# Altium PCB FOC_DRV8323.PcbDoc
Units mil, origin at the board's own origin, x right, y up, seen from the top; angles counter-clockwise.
Board outline 1427.17 x 915.35 mil, 6 copper layers (Top Layer, GND1, GND, Sign, GND2, Bottom Layer), stack 32.112 mil thick; 72 components, 67 nets, 293 pads, 283 vias.
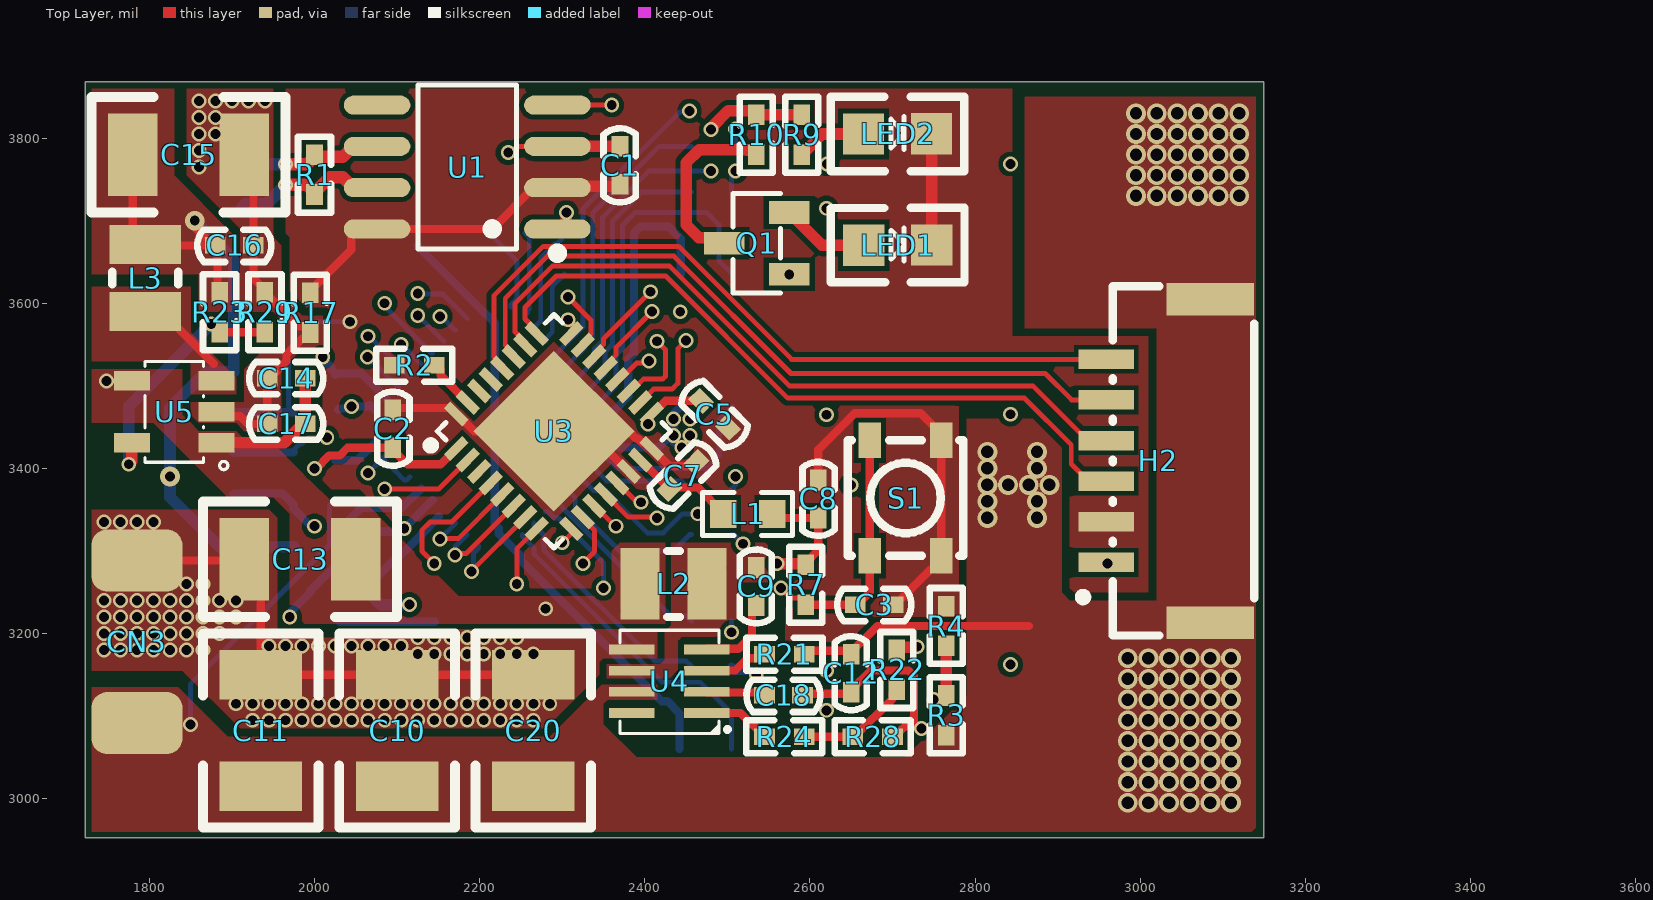
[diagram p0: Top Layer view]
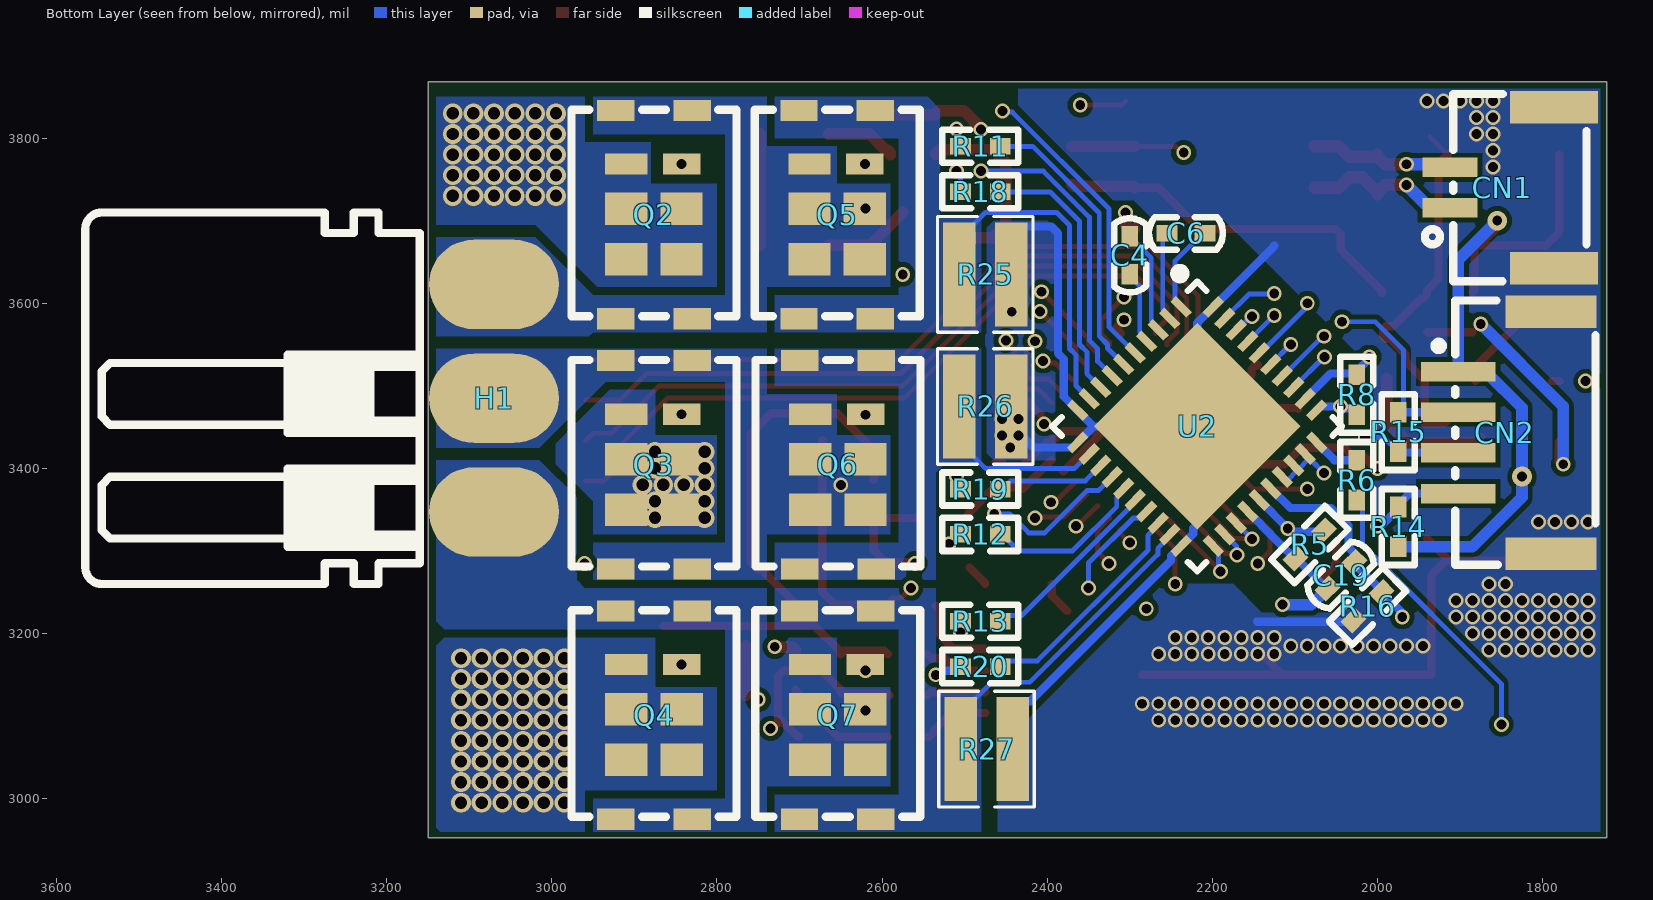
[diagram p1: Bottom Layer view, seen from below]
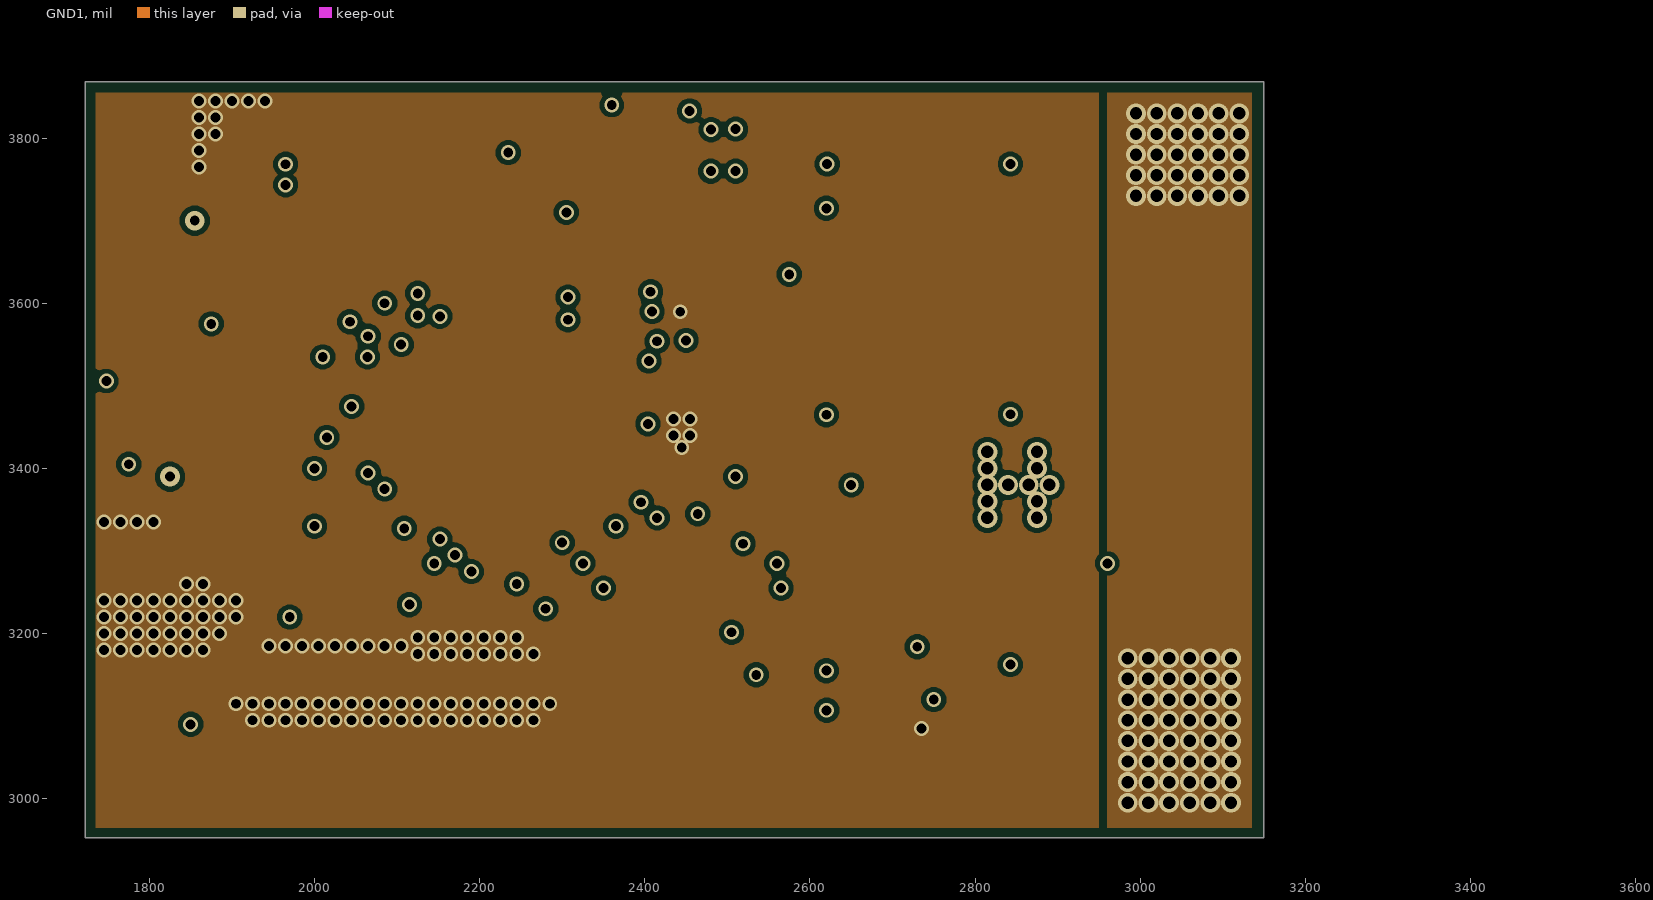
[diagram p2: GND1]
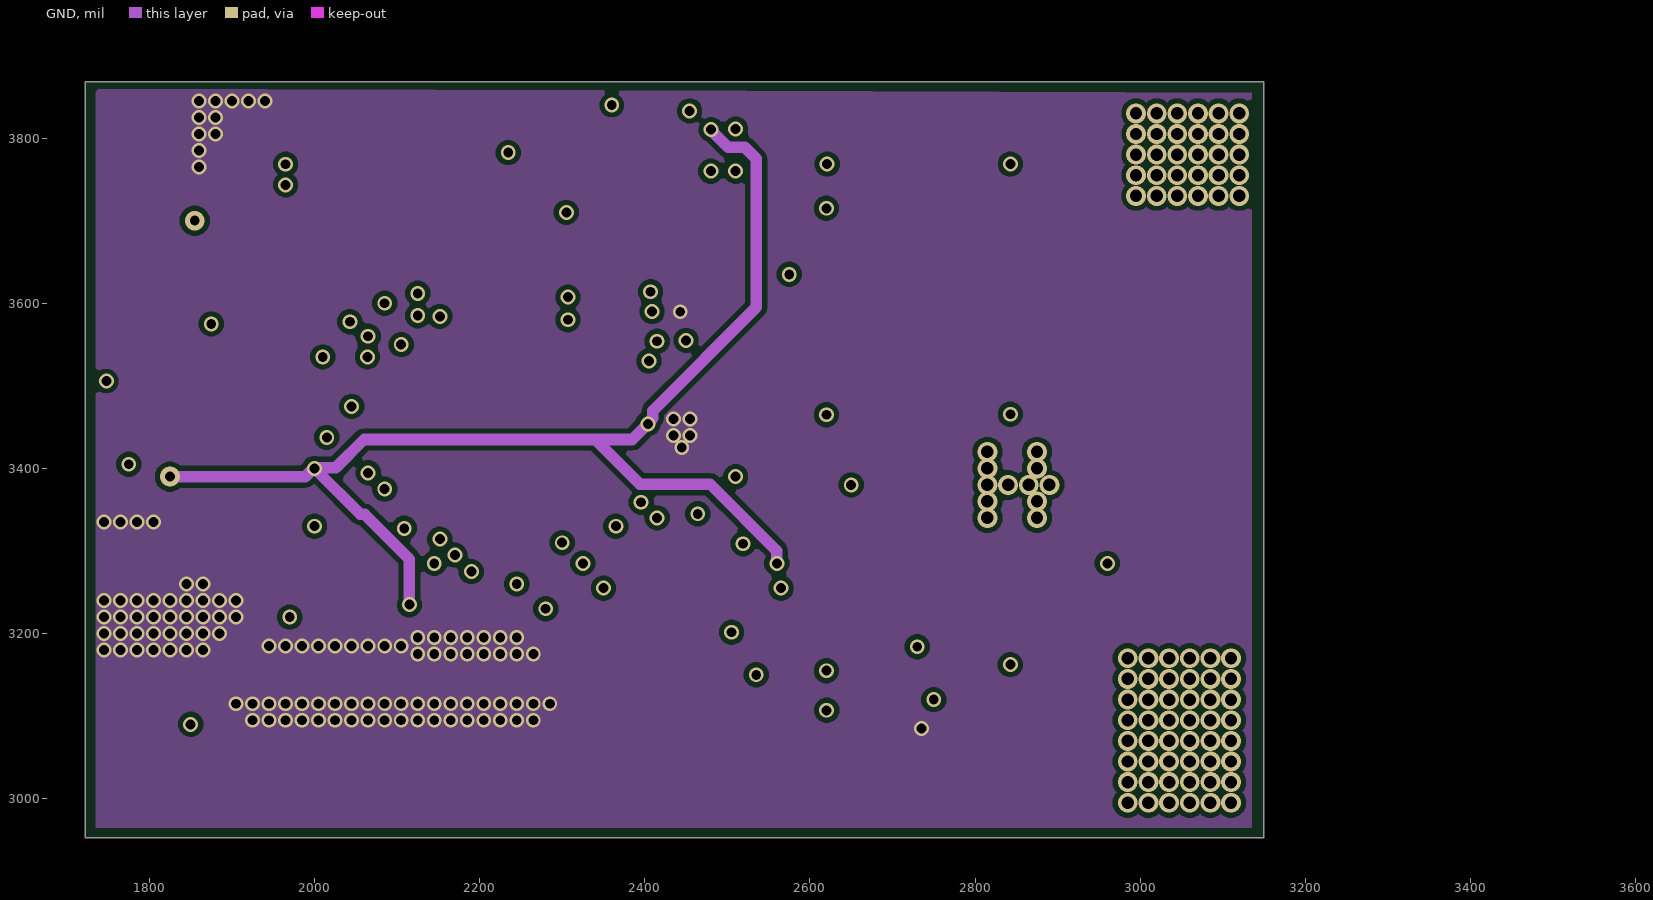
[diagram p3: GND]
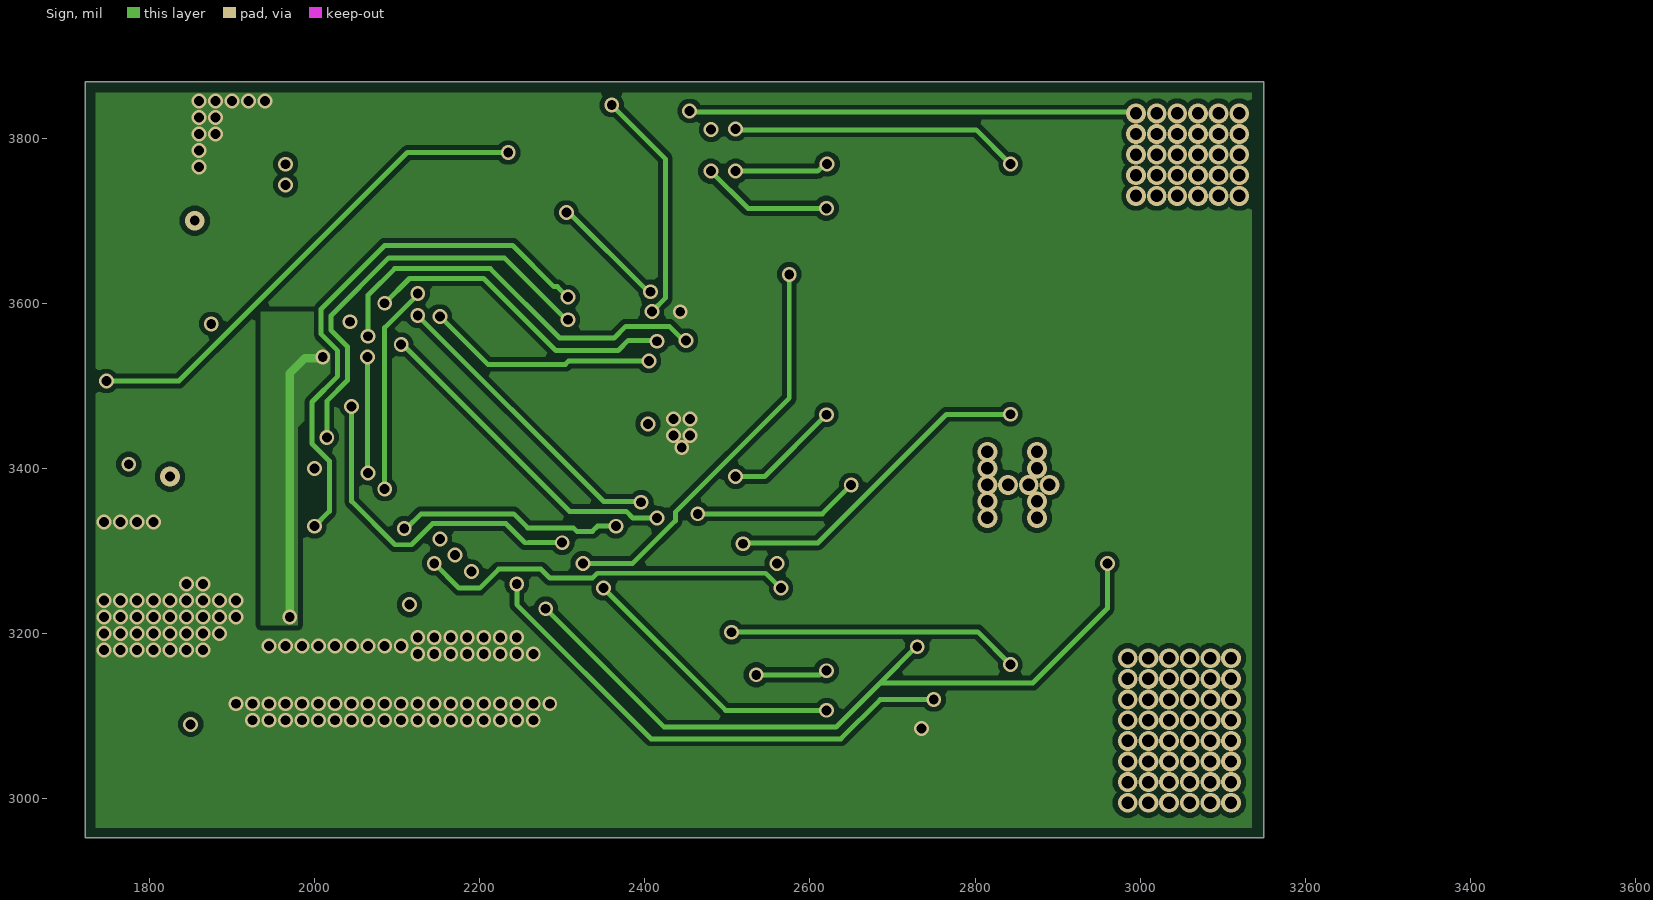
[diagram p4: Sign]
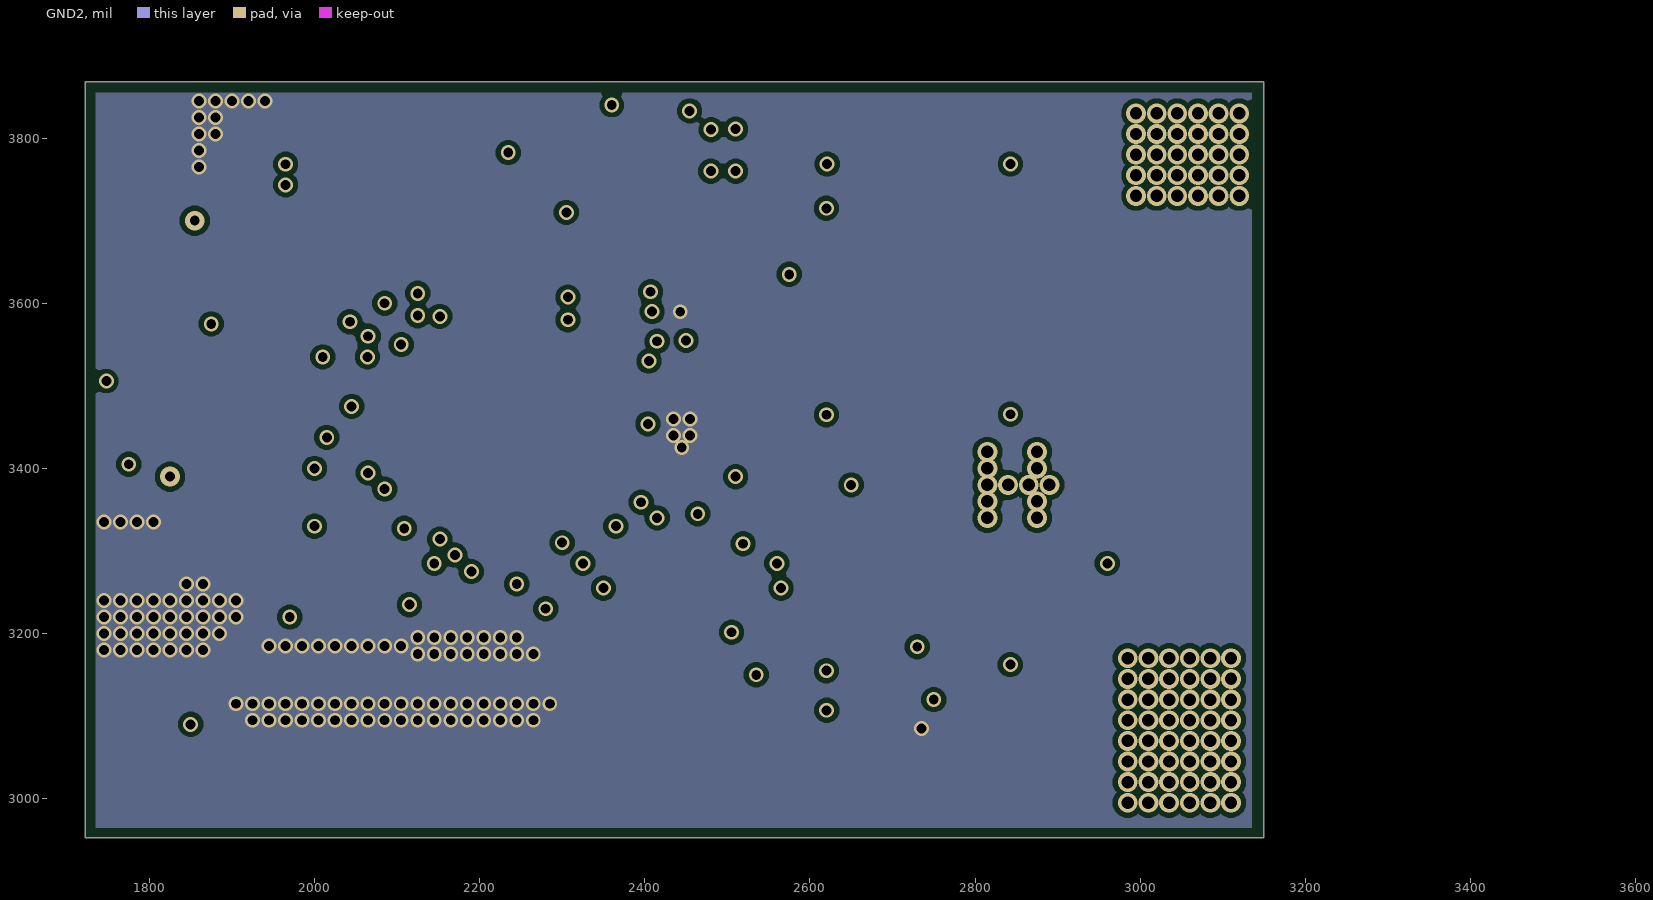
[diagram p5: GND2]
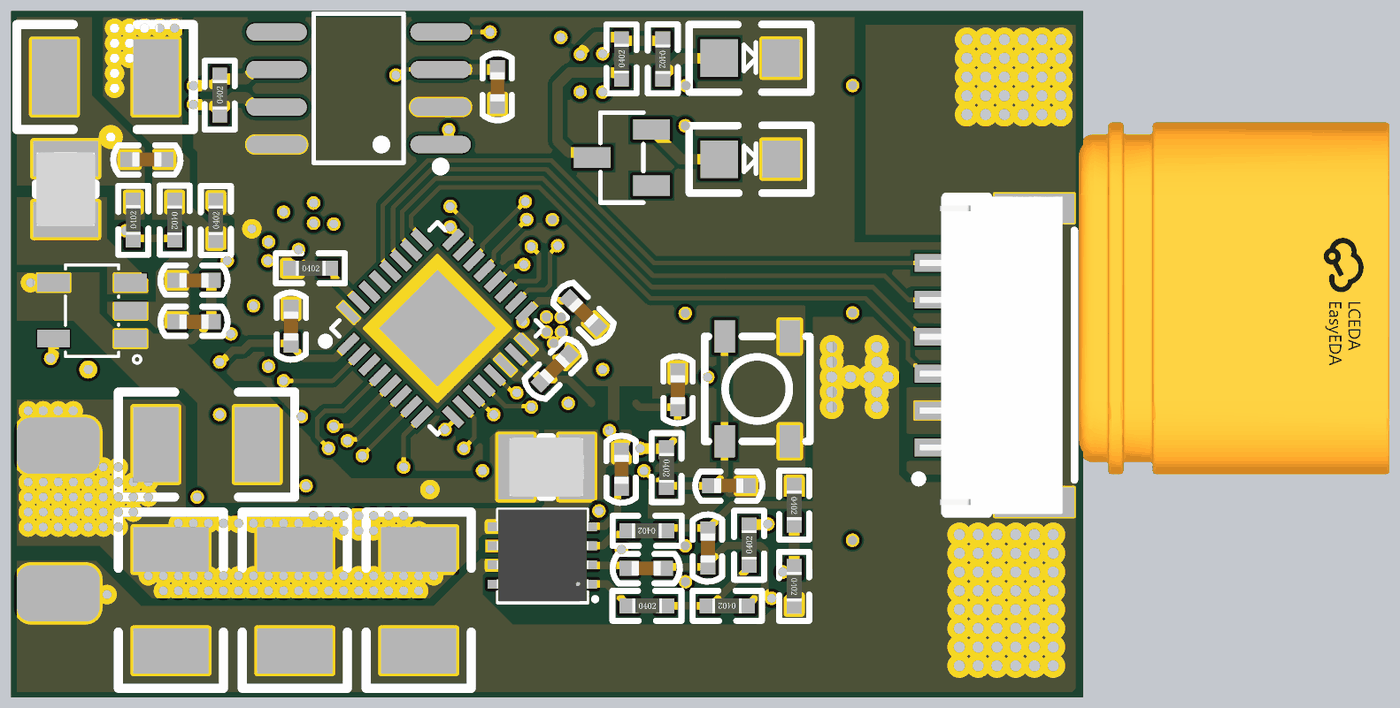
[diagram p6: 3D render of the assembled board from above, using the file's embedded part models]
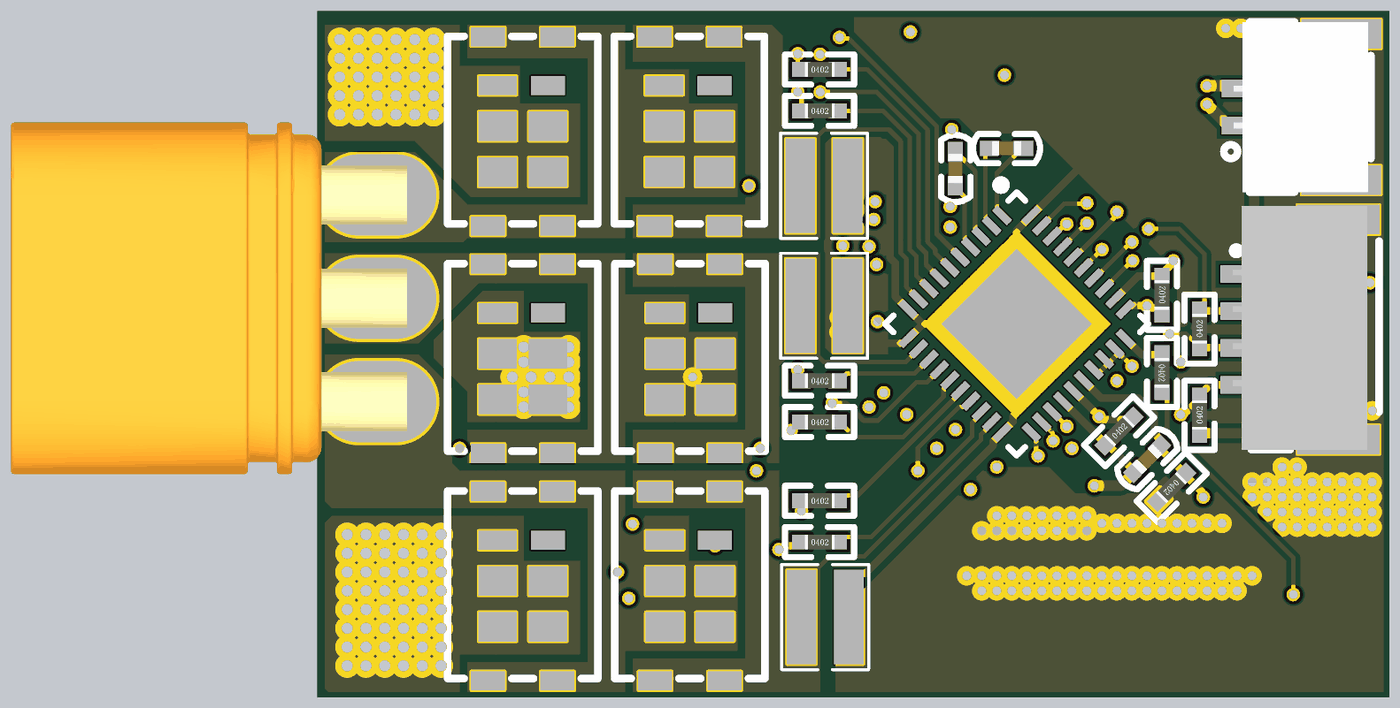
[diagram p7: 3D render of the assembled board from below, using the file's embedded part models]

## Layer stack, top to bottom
Top Solder: solder mask 0.4, Solder Resist, Dk 3.5
Top Layer: signal copper 1.4
Dielectric 2: prepreg 2.8, PP-006, Dk 4.1
GND1: signal copper 1.378
Dielectric 4: prepreg 2.8, PP-006, Dk 4.1
GND: signal copper 1.378
Dielectric 1: dielectric 12.6, FR-4, Dk 4.8
Sign: signal copper 1.378
Dielectric 5: prepreg 2.8, PP-006, Dk 4.1
GND2: signal copper 1.378
Dielectric 3: prepreg 2.8, PP-006, Dk 4.1
Bottom Layer: signal copper 1.4
Bottom Solder: solder mask 0.4, Solder Resist, Dk 3.5

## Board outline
1722.44,2952.76 1722.44,3868.11 3149.61,3868.11 3149.61,2952.76

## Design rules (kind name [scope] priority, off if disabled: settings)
Clearance [All] p1: gap=6 ignorepadtopadclearanceinfootprint=FALSE except(0: Arc-Hole Track-Hole SMDPad-Hole THPad-Hole Via-Hole Fill-Hole Poly-Hole Region-Hole Text-Hole)
DiffPairsRouting [All] p1: maxlimit=10 minlimit=10 mostfreqgap=10 toplayer_minwidth=15 toplayer_maxwidth=15 toplayer_prefwidth=15 midlayer1_minwidth=15 midlayer1_maxwidth=15 midlayer1_prefwidth=15 midlayer2_minwidth=15 midlayer2_maxwidth=15 midlayer2_prefwidth=15 midlayer3_minwidth=15 midlayer3_maxwidth=15 midlayer3_prefwidth=15 midlayer4_minwidth=15 midlayer4_maxwidth=15 midlayer4_prefwidth=15 bottomlayer_minwidth=15 bottomlayer_maxwidth=15 bottomlayer_prefwidth=15 maxuncoupledlength=500
HoleToHoleClearance [All] p1: gap=4 allowstackedmicrovias=TRUE
MinimumSolderMaskSliver [All] p1: minsoldermaskwidth=0
PlaneClearance [All] p1: clearance=8
PlaneConnect [All] p1: planeconnectstyle=Direct reliefexpansion=20 reliefentries=4 reliefconductorwidth=10 reliefairgap=10
PolygonConnect [All] p1: connectstyle=Direct reliefconductorwidth=10 reliefentries=4 polygonreliefangle="90 Angle" airgapwidth=10
RoutingVias [All] p1: holewidth=12 width=16 viastyle="Through Hole" minholewidth=10 minwidth=16 maxholewidth=28 maxwidth=50
SilkToSilkClearance [All] p1: silktosilkclearance=0
SilkToSolderMaskClearance [IsPad] p1: minsilkscreentomaskgap=0 clearancetoexposedcopper=TRUE
SolderMaskExpansion [All] p1: expansion=4 istentingtop=FALSE
Width [All] p1: maxlimit=14 minlimit=6 preferedwidth=10
23 further rules are at their usual default settings.

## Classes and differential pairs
differential pair CAN: +CAN_P -CAN_N

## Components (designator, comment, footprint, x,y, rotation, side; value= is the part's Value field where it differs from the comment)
C1 "100nF" c0402 2370,3745 r90 top
C2 "100nF" c0402 2095,3470 r270 top
C3 "100nF" c0402 2700,3235 r180 top
C4 "1uF" c0402 2300,3680 r270 bottom
C5 "100nF" c0402 2500,3450 r135 top
C6 "47nF" c0402 2210,3685 r0 bottom
C7 "100nF" c0402 2461.82,3406.82 r225 top
C8 "100nF" c0402 2610,3385 r270 top
C9 "100nF" c0402 2535,3235 r90 top
C10 "10uF" 1210 2100,3150 r270 top
C11 "10uF" 1210 1935,3150 r270 top
C12 "100nF" c0402 2650,3130 r90 top
C13 "10uF" 1210 1915,3290 r0 top
C14 "100nF" c0402 1943.82,3508.9 r0 top
C15 "10uF" 1210 1915,3780 r180 top
C16 "100nF" c0402 1925,3670 r180 top
C17 "1uF" c0402 1943.82,3453.9 r0 top
C18 "100nF" c0402 2590,3125 r180 top
C19 "100nF" c0402 2060,3255 r135 bottom
C20 "10uF" 1210 2265,3150 r270 top
CN1 "卧式CAN" "GH1.25 2P 卧式" 1849.16,3740 r90 bottom
CN2 "卧式STLINK" CONN-SMD_4P-P1.25_GH1.25-4P 1846.1,3443.35 r90 bottom
CN3 "XT30_1" XT30卧式焊盘 1785,3190 r0 top
H1 "MR30-M" MR30 3070,3485 r270 bottom
H2 "卧式GH1.25 6PIN" CONN-SMD_6P-P1.25_XYECONN_XY-GH1.25-6A61 3022.01,3409.13 r90 top
L1 "1008屏蔽电感" R0603 3889.19,3386.01 r180 top
L2 "1008屏蔽电感" IND-SMD_L2.5-W2.0 2435,3260 r0 top
L3 "1008屏蔽电感" IND-SMD_L2.5-W2.0 1795,3630.48 r270 top
LED1 "LED" led0805 2665.2,3670.35 r0 top
LED2 "LED" led0805 2665,3805 r0 top
Q1 "SS8050" SOT-23-3_L2.9-W1.3-P1.90-LS2.4-BR 2316.65,3827.51 r0 top
Q2 "IRF7480MTRPBF" TRS-SMD_IRF7480MTRPBF 2876.3,3707.44 r270 bottom
Q3 "IRF7480MTRPBF" TRS-SMD_IRF7480MTRPBF 2876.3,3404.31 r270 bottom
Q4 "IRF7480MTRPBF" TRS-SMD_IRF7480MTRPBF 2876.26,3101.18 r270 bottom
Q5 "IRF7480MTRPBF" TRS-SMD_IRF7480MTRPBF 2654.36,3707.44 r270 bottom
Q6 "IRF7480MTRPBF" TRS-SMD_IRF7480MTRPBF 2653.47,3404.31 r270 bottom
Q7 "IRF7480MTRPBF" TRS-SMD_IRF7480MTRPBF 2653.74,3101.18 r270 bottom
R1 "120Ω" R0402 2000,3731.8 r90 top
R2 "10K" R0402 2096.8,3525 r0 top
R3 "10K" R0402 2765,3125 r270 top
R4 "1K" R0402 2765,3233.2 r270 top
R5 "200k" R0402 2099.08,3290.92 r135 bottom
R6 "200k" R0402 2025,3410 r270 bottom
R7 "10K" R0402 2595,3283.2 r270 top
R8 "200k" R0402 2025,3465 r90 bottom
R9 "2K" R0402 2590,3828.2 r270 top
R10 "2KΩ" R0402 2535,3780 r90 top
R11 "2.2R" R0402 2505,3790 r180 bottom
R12 "2.2R" R0402 2505,3320 r180 bottom
R13 "2.2R" R0402 2505,3215 r180 bottom
R14 "10KΩ" R0402 1975,3305 r90 bottom
R15 "10KΩ" R0402 1975,3420 r90 bottom
R16 "0" R0402 1995,3250 r315 bottom
R17 "0" R0402 1994.88,3564.59 r90 top
R18 "2.2R" R0402 2505,3735 r180 bottom
R19 "2.2R" R0402 2505,3375 r180 bottom
R20 "2.2R" R0402 2505,3160 r180 bottom
R21 "10KΩ" R0402 2593.2,3175 r180 top
R22 "43KΩ" R0402 2705,3131.8 r90 top
R23 "232KΩ" R0402 1885,3565 r90 top
R24 "51KΩ" R0402 2545,3075 r0 top
R25 "0.001" R0612 2475,3635 r0 bottom
R26 "0.001" R0612 2475,3475 r0 bottom
R27 "0.001" R0612 2473.5,3060 r0 bottom
R28 "8.2KΩ" R0402 2700,3075 r180 top
R29 "51KΩ" R0402 1940,3613.2 r270 top
S1 "SW" KEY_SMD 2715.86,3364.14 r90 top
U1 "SN65HVD1050DR" SOIC-8_L4.9-W3.9-P1.27-LS6.0-BL 2185,3765 r90 top
U2 "DRV8323HRTAR" QFN-40_L6.0-W6.0-P0.50-BL-EP4.5 2226.52,3458.96 r315 bottom
U3 "STM32G431KBU3" UFQFPN-32_L5.0-W5.0-P0.50-BL-EP3.5 2286.98,3441.98 r315 top
U4 "MP9943" "QFN-8 3x3" 2475,3103.82 r180 top
U5 "TLV62569DBVR" SOT-23-5_L3.0-W1.7-P0.95-LS2.8-BR 1830,3465 r0 top

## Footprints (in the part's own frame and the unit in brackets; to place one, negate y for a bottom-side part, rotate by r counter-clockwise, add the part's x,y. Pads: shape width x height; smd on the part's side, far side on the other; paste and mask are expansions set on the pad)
1210 [mil]
  rect 60x100 smd: 1(0,0) 2(135,0)
  silkscreen extent -50,-70 185,70, body extent 4,-49 130,49, height 30
c0402 [mil]
  rect 25x20 smd: 1(-1,0) 2(45,0)
  silkscreen extent -23,-19 67,20, body extent 2,-10 42,10, height 20
CONN-SMD_4P-P1.25_GH1.25-4P [mm]
  rect 0.6x2.3 smd mask+0.051: 1(1.875,1.425) 2(0.625,1.425) 3(-0.625,1.425) 4(-1.875,1.425)
  rect 1x2.8 smd mask+0.051: 5(-3.725,-1.425) 6(3.725,-1.425)
  silkscreen extent -4.06,-2.8 4.06,2.16, body extent -4.07,-2.4 4.19,2.15, height 4.13
CONN-SMD_6P-P1.25_XYECONN_XY-GH1.25-6A61 [mm]
  rect 0.6x1.7 smd paste+0 mask+0.05: 1(-3.125,1.6) 2(-1.875,1.6) 3(-0.625,1.6) 4(0.625,1.6) 5(1.875,1.6) 6(3.125,1.6)
  rect 1x2.7 smd paste+0 mask+0.05: 7(4.975,-1.6) 8(-4.975,-1.6)
  silkscreen extent -5.38,-2.95 5.38,2.44, body extent -5.38,-2.55 5.39,2.3, height 4.34
"GH1.25 2P 卧式" [mm]
  rect 0.6x1.7 smd mask+0.051: 1(-0.625,1.602) 2(0.625,1.602)
  rect 1x2.7 smd mask+0.051: 3(2.475,-1.602) 4(-2.475,-1.598)
  silkscreen extent -2.88,-2.6 2.88,2.37, body extent -2.88,-2.51 2.88,2.05, height 4.13
IND-SMD_L2.5-W2.0 [mm]
  rect 1.2x2.2 smd: 1(1.028,0) 2(-1.028,0)
  silkscreen extent -0.2,-1.02 0.2,1.02, body extent -1.26,-1 1.26,1, height 1.2
KEY_SMD [mm]
  rect 1.1x0.7 smd: 1(-1.775,-1.1) 1(1.775,-1.1) 2(-1.775,1.1) 2(1.775,1.1)
  silkscreen extent -1.78,-1.78 1.78,1.78
led0805 [mil] "1/8W"
  rect 50x50 smd: 1(0,0) 2(82.3,0.2)
  silkscreen extent -40,-45 122,45, body extent 2,-25 80,25, height 20
MR30 [mm]
  oval 2.75x4 smd: 1(3.5,0) 2(0,0) 3(-3.5,0)
  silkscreen extent -5.72,-12.57 5.71,-2.29, body extent -5.95,-12.39 5.95,1.01, height 2.45
"QFN-8 3x3" [mm]
  rect 1.4x0.3 smd: 1(0,0) 2(0,-0.65) 3(0,-1.3) 4(0,-1.95) 5(2.3,-1.95) 6(2.3,-1.3) 7(2.3,-0.65) 8(2.3,0)
  silkscreen extent -0.64,-2.54 2.67,0.64, body extent -0.41,-2.53 2.69,0.57, height 0.94
QFN-40_L6.0-W6.0-P0.50-BL-EP4.5 [mm]
  rect 0.25x0.7 smd paste-100 mask+0.051: 1(-2.25,-2.659) 2(-1.75,-2.659) 3(-1.25,-2.659) 4(-0.75,-2.659) 5(-0.25,-2.659) 6(0.25,-2.659) 7(0.75,-2.659) 8(1.25,-2.659) 9(1.75,-2.659) 10(2.25,-2.659) 21(2.25,3.241) 22(1.75,3.241) 23(1.25,3.241) 24(0.75,3.241) 25(0.25,3.241) 26(-0.25,3.241) 27(-0.75,3.241) 28(-1.25,3.241) 29(-1.75,3.241) 30(-2.25,3.241)
  rect 0.7x0.25 smd paste-100 mask+0.051: 11(2.95,-1.958) 12(2.95,-1.459) 13(2.95,-0.958) 14(2.95,-0.459) 15(2.95,0.042) 16(2.95,0.541) 17(2.95,1.042) 18(2.95,1.541) 19(2.95,2.041) 20(2.95,2.541) 31(-2.95,2.541) 32(-2.95,2.041) 33(-2.95,1.541) 34(-2.95,1.042) 35(-2.95,0.541) 36(-2.95,0.042) 37(-2.95,-0.459) 38(-2.95,-0.958) 39(-2.95,-1.459) 40(-2.95,-1.958)
  rect 4.5x4.5 smd paste-100 mask+0.051: 41(0,0.292)
  silkscreen extent -3.15,-3.56 3.15,3.44
R0402 [mil] "1/16W"
  rect 25x20 smd: 1(0,0) 2(48.2,0)
  silkscreen extent -22,-20 70,20, body extent 5,-10 44,10, height 14
R0603 [mil]
  rect 31.75x34.02 smd paste-3937.01 mask+2: 1(1334.87,41.01) 2(1394.19,41.01)
  silkscreen extent 1310,15 1419,67, body extent 1334,24 1396,56, height 18
R0612 [mm]
  rect 1x3.2 smd paste+0 mask+0.051: 1(-0.8,0) 2(0.8,0)
  silkscreen extent -1.47,-1.78 1.47,1.78
SOIC-8_L4.9-W3.9-P1.27-LS6.0-BL [mm]
  oval 0.588x2.045 smd mask+0.051: 1(-1.905,-2.772) 2(-0.635,-2.772) 3(0.635,-2.772) 4(1.905,-2.772) 5(1.905,2.772) 6(0.635,2.772) 7(-0.635,2.772) 8(-1.905,2.772)
  silkscreen extent -2.8,-2.92 2.53,1.52, body extent -2.45,-3 2.45,3, height 1.75
SOT-23-3_L2.9-W1.3-P1.90-LS2.4-BR [mm]
  rect 1.25x0.7 smd: 1(6.562,-4.885) 2(6.562,-2.985) 3(4.562,-3.935)
  silkscreen extent 4.84,-5.46 6.29,-2.41, body extent 4.19,-5.39 6.99,-2.49, height 1.3
SOT-23-5_L3.0-W1.7-P0.95-LS2.8-BR [mm]
  rect 1.1x0.6 smd paste+0 mask+0.051: 1(1.3,-0.861) 2(1.3,0.089) 3(1.3,1.039) 4(-1.3,1.039) 5(-1.3,-0.861)
  silkscreen extent -0.9,-1.69 1.65,1.64
TRS-SMD_IRF7480MTRPBF [mm]
  rect 0.65x1.15 smd paste+0 mask+0.051: 1(-1.555,0.85) 7(-3.205,1.175) 8(-3.205,-1.175) 9(3.205,-1.175) 10(3.205,1.175)
  rect 1x1.3 smd paste+0 mask+0.051: 2(-0.175,0.85) 3(1.375,0.85) 4(1.375,-0.85) 5(-0.175,-0.85)
  rect 0.65x1.3 smd paste+0 mask+0.051: 6(-1.555,-0.85)
  silkscreen extent -3.22,-2.54 3.13,2.54
UFQFPN-32_L5.0-W5.0-P0.50-BL-EP3.5 [mm]
  rect 0.28x0.8 smd paste-100 mask+0.051: 1(-1.75,-2.392) 2(-1.25,-2.392) 3(-0.75,-2.392) 4(-0.25,-2.392) 5(0.25,-2.392) 6(0.75,-2.392) 7(1.25,-2.392) 8(1.75,-2.392) 17(1.75,2.609) 18(1.25,2.608) 19(0.75,2.609) 20(0.25,2.608) 21(-0.25,2.608) 22(-0.75,2.608) 23(-1.25,2.608) 24(-1.75,2.608)
  rect 0.8x0.28 smd paste-100 mask+0.051: 9(2.5,-1.642) 10(2.5,-1.142) 11(2.5,-0.642) 12(2.5,-0.142) 13(2.5,0.358) 14(2.5,0.858) 15(2.5,1.358) 16(2.5,1.858) 25(-2.5,1.858) 26(-2.5,1.358) 27(-2.5,0.858) 28(-2.5,0.358) 29(-2.5,-0.142) 30(-2.5,-0.642) 31(-2.5,-1.142) 32(-2.5,-1.642)
  rect 3.5x3.5 smd paste-100 mask+0.051: 33(0,0.108)
  silkscreen extent -2.54,-3.01 2.54,2.65
XT30卧式焊盘 [mil]
  rrect50% 110x75 smd: 1(0,98.43) 2(0,-98.43)

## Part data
C1 C9 C12 C14 C15 C16 C17 C18: library part 0402贴片电容, "贴片电容0402"
C2 C3 C4 C5 C6 C7 C8 C19: library part CC0201JRX7R9BB101
C10 C11 C13 C20: library part 1210贴片电容, "1210贴片电容"
H1: BOM_Manufacturer=AMASS(艾迈斯)
LED1 LED2: library part 0805贴片LED, "0805贴片LED"
Q1: library part 2N2222, "三极管"
R1 R10 R14 R15 R21 R22 R23 R24 R28 R29: library part 0402贴片电阻, "0402贴片电阻"
R2 R3 R4 R5 R6 R7 R8 R9 R16 R17: library part 2.2R, BOM_Manufacturer=UniOhm, BOM_Manufacturer Part=0603WAJ022JT5E
R11 R12 R13 R18 R19 R20: BOM_Manufacturer=UniOhm, BOM_Manufacturer Part=0603WAJ022JT5E
R25 R26 R27: library part 0.0005, BOM_Manufacturer=RALEC(旺诠), BOM_Manufacturer Part=LR2512-23R0005J4
S1: "开关"
U1: "CAN芯片", JLCPCB Part Class="Extended Part", LCSC Part Name=4.5V~5.5V, Manufacturer=TI(德州仪器), Operating Temperature=-40℃~+125℃, Supply Current=50mA

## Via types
v1: diameter 18, hole 12, Top Layer to Bottom Layer, 191 vias
v2: diameter 24, hole 15, Top Layer to Bottom Layer, 90 vias
v3: diameter 24, hole 12, Top Layer to Bottom Layer, 2 vias

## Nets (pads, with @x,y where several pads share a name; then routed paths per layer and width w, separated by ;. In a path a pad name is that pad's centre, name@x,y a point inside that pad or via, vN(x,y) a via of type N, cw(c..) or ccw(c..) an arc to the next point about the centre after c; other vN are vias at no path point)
5V: C1.2 C13.2 C14.2 C17.2 H2.1 L2.2 R22.2 U1.3 U5.1 U5.4 | length 1962
  Top Layer w6: v1(2234.68,3782.51) 2237.39,3782.51 2244.88,3790 U1.3
  Top Layer w10: U5.4 U5.4@1788.66,3505.91 ; U5.1@1874.37,3437.91 U5.1 ; C13.2@2050,3310 C13.2 2050,3285 C13.2@2065,3270 ; L2.2@2375.9,3227.24 2394.52,3245.86 L2.2
  Top Layer w14: U5.1 1924.73,3431.1 1924.94,3430.9 1963.32,3430.9 1986.32,3453.9 C17.2 C14.2 ; U1.3 C1.2 ; R22.2 2705,3180.23 2708,3183.23 2729.23,3183.23 v1(2730,3184)
  Sign w6: v1(1748.03,3505.76) 1835.76,3505.76 2112.51,3782.51 v1(2234.68,3782.51) ; v1(2280,3230) 2423.46,3086.54 2631.54,3086.54 2685,3140 ; v1(2730,3184) 2729,3184 2685,3140 ; v1(2960.27,3284.92) 2960.27,3230.27 2870,3140 2685,3140
+3.3V: C2.2 C5.2 C8.2 C15.2 C16.2 C19.1 CN2.1 L1.1 L3.2 R5.1 R7.1 R9.1 R10.2 R14.1 R23.2 U2.24 U3.1 U3.17 | length 3180.9
  Top Layer w10: C15.2 1780,3685.96 L3.2 1795.96,3670 C16.2@1877.5,3670 ; v3(1855,3700) 1856.15,3698.85 1856.15,3691.35 C16.2@1877.5,3670 ; R23.2 1882.5,3615.7 1882.5,3667.5 C16.2 C16.2@1877.5,3670 ; v1(2000,3400) 2002.16,3400 2017.84,3415.67 2030.62,3415.67 2039.95,3425 C2.2 2095,3422.5 2112.5,3405 2152.56,3405 U3.1 U3.1@2164.44,3416.88 ; U3.17 2409.04,3465.89 2424.97,3481.82 2457.57,3481.82 2459.34,3483.59 2466.41,3483.59 C5.2 ; L1.1 2559.32,3340 C8.2 2610,3300.7 R7.1@2595,3285.7
  Top Layer w14: v1(2480.26,3810.24) 2481.02,3811.01 2481.02,3813.14 2500.89,3833 2532,3833 2535,3830 R10.2 R9.1 ; v1(2560,3285) 2560.38,3284.62 2593.92,3284.62 R7.1@2595,3285.7
  GND w14: v3(1825,3390) 1988.92,3390 1998.92,3400 v1(2000,3400) 2000.77,3400.77 2025.77,3400.77 2060,3435 2340,3435 ; v1@2001.85,3400 2001.31,3399.46 2001.31,3398.69 2055.65,3344.35 2060.65,3344.35 2115,3290 v1(2115,3235) ; v1(2403.82,3453.89) 2384.93,3435 2340,3435 ; v1@2405.67,3453.13 2404.58,3454.21 2404.58,3455.74 2409.58,3460.74 2409.58,3469.58 2535,3595 2535,3775 2521,3789 2500.89,3789 2480.26,3809.63 v1(2480.26,3810.24) ; v1@2560,3285.54 2560,3300 2479,3381 2394,3381 2340,3435
  Bottom Layer w10: C19.1 2061.58,3254.29 2098.21,3290.92 2100.13,3290.92 2116.58,3307.37 2117.03,3307.37 2129.91,3320.25 2129.91,3320.7 U2.24@2150.9,3341.69
  Bottom Layer w14: v3(1855,3700) 1902.2,3652.8 CN2.1 1868.74,3517.17 1825,3473.43 v3(1825,3390) 1825,3365 1885,3305 R14.1 ; C19.1 2080,3235 v1(2115,3235)
AGND: C19.2 R8.2 R16.1 U2.26 U2.32 | length 699.5
  Sign w10: v1(1970,3220) 1970,3515 1988.47,3533.47 2008.47,3533.47 v1(2010,3535)
  Bottom Layer w10: v1(1970,3220) 1971.15,3221.15 1971.15,3226.15 R16.1 1995,3251.82 2028.18,3285 C19.2 2026.41,3288.59 2026.41,3295.66 2035.08,3304.33 2035.08,3330.93 2056.06,3351.91 2105.55,3351.91 U2.26 ; v1(2010,3535) 2010,3532.84 2020,3522.84 2020,3520.7 2025,3515.7 R8.2 2026.8,3515 2056.81,3515 U2.32
CAL: R8.1 U2.31 U3.9 | length 484.7
  Top Layer w6: v1(2300,3310) 2312,3322 2312,3325.55 U3.9
  Sign w6: v1(2045,3475) 2045,3360 2097.5,3307.5 2117.5,3307.5 2143,3333 2232,3333 2255.03,3309.97 2260,3309.97 ; 2260.03,3310 v1(2300,3310)
  Bottom Layer w10: R8.1@2028.41,3470.91 2030,3472.5 2040.88,3472.5 2044.86,3476.49 v1@2045,3476.49 ; v1(2045,3475) 2065.89,3475 2067.38,3476.49 2067.49,3476.49 U2.31
CAN_N: CN1.2 R1.2 U1.6 | length 174.1
  Top Layer w15: v1(1965,3768.4) 1990.9,3768.4 2000,3777.5 R1.2 ; R1.2@2002.5,3777.5 2034.31,3777.5 2046.81,3790 U1.6
  Bottom Layer w15: CN1.2 1916.02,3768.4 v1(1965,3768.4)
CAN_P: CN1.1 R1.1 U1.7 | length 194.2
  Top Layer w15: v1(1965,3743.4) 1990.9,3743.4 R1.1@2000,3734.3 ; R1.1 R1.1@2000,3734.3 ; U1.7 2046.81,3740 2034.31,3752.5 2018.2,3752.5 R1.1@2000,3734.3
  Bottom Layer w15: CN1.1 1916.54,3719.7 1941.3,3719.7 v1(1965,3743.4)
DGND: C1.1 C2.1 C3.1 C5.1 C7.1 C8.1 CN2.2 H2.2 LED1.2 LED2.2 R2.1 R4.1 R15.2 R17.2 S1.1 U1.2 U1.8 U3.14 U3.16 U3.32 U3.33 | length 1733.9
  Top Layer w10: R17.2 1994.88,3615.29 2044.65,3665.06 2044.65,3683.93 2050.73,3690 U1.8 2215.47,3690 2265.47,3740 U1.2 ; C2.1@2095.9,3471.9 2097.12,3473.12 2164.44,3473.12 U3.32 2172.41,3465.88 2193.29,3445 U3.33 U3.33@2331.75,3445 ; U3.14 U3.33@2331.75,3445 ; C7.1 2455.46,3407.53 2450.9,3402.97 2430.18,3402.97 2409.04,3424.11 U3.16 2401.08,3431.35 2396.57,3431.35 2391.71,3436.22 2389.14,3436.22 2380.36,3445 U3.33@2331.75,3445 ; C5.1@2500.71,3447.5 C5.1 ; C8.1 2610,3422.46 2654.21,3466.68 2734.38,3466.68 2759.16,3441.9 2759.16,3434.02 2759.16,3294.26 2759.16,3286.38 2750.38,3277.61 2746.11,3277.61 2703.5,3235 C3.1
  Top Layer w14: U1.2 2295.9,3741.75 2367.75,3741.75 C1.1 ; LED1.2 LED2.2@2747.5,3805
  Bottom Layer w6: R15.2 1968.23,3474.97 1968.23,3543.23 2002.62,3577.62 v1(2042.81,3577.62)
  Bottom Layer w10: CN2.2 1902.32,3468.08 1974.88,3468.08 R15.2
DVDD: U2.27 U2.28 U2.29 U2.33 | length 275.5
  Sign w6: v1(2064.17,3535) 2064.41,3534.76 2064.41,3395.16 v1(2065.01,3394.56)
  Bottom Layer w6: v1(2064.17,3535) 2064.83,3535 2101.48,3498.34 U2.33 ; v1(2065.01,3394.56) 2065.01,3394.72 2080.52,3410.24 2080.52,3410.88 2083.72,3410.88 2094.92,3399.67 U2.28@2097.64,3399.67 ; U2.29@2083.72,3413.59 U2.29 ; U2.28 U2.28@2097.64,3399.67 ; U2.27 2111.56,3385.76 2108.84,3385.76 2097.64,3396.96 U2.28@2097.64,3399.67
FDCAN_RX: U1.4 U3.21 | length 432.4
  Top Layer w6: U1.4@2305,3845 2310,3840 v1(2360,3840) ; U3.21 2352.63,3524.74 2365,3537.11 2365,3546.18 v1(2408.82,3590)
  Sign w6: v1(2360,3840) 2425,3775 2425,3606.18 v1(2408.82,3590)
FDCAN_TX: U1.1 U3.22 | length 281.5
  Top Layer w6: U1.1 U1.1@2297.43,3686.72 ; U3.22 2338.71,3539.03 2350,3550.31 2350,3556.93 v1(2407,3613.93)
  Top Layer w14: U1.1 2300.77,3690 2305,3694.23 v1(2305,3710)
  Sign w6: v1(2305,3710) 2307.97,3710 2404.03,3613.93 v1(2407,3613.93)
M0_AH: U2.34 U3.18 | length 677.5
  Top Layer w6: U3.18 2410.59,3496 2433.02,3496 2440,3502.98 2440,3545 v1(2450,3555)
  Sign w6: v1(2065,3560) 2065,3610 2097,3642 2213,3642 2297,3558 2363,3558 2377,3572 2429.75,3572 2446.75,3555 v1(2450,3555)
  Bottom Layer w6: v1(2065,3560) 2066.24,3560 2114.16,3512.09 U2.34
M0_AL: U2.35 U3.12 | length 505.4
  Top Layer w6: U3.12 2380.07,3341 2414,3341 v1(2415,3340)
  Sign w6: v1(2105,3550) 2106.92,3550 2308.92,3348 2377.46,3348 2385.46,3340 v1(2415,3340)
  Bottom Layer w6: v1(2105,3550) 2105.33,3550 U2.35
M0_BH: U2.36 U3.19 | length 568.1
  Top Layer w6: U3.19 2384.03,3493.73 2398.3,3508 2421.49,3508 2425,3511.51 2425,3544 v1(2415,3554)
  Sign w6: v1(2085,3600) 2115,3630 2205,3630 2292.29,3542.71 2367.71,3542.71 2380,3555 2414,3555 v1(2415,3554)
  Bottom Layer w6: v1(2085,3600) 2085,3597.29 2089,3593.29 2089,3591.96 2141.03,3539.93 U2.36
M0_BL: U2.37 U3.13 | length 448
  Top Layer w6: U3.13 2367.1,3382.35 2388.15,3361.3 2393.29,3361.3 v1(2395.59,3359)
  Sign w6: v1(2125,3585) 2350,3360 2394.59,3360 v1(2395.59,3359)
  Bottom Layer w6: v1(2125,3585) 2125.51,3585 2156.66,3553.85 U2.37
M0_CH: U2.38 U3.20 | length 352.4
  Top Layer w6: U3.20 2370.11,3507.64 2390.17,3527.7 2402.7,3527.7 v1(2405,3530)
  Sign w6: v1(2151.89,3584.07) 2209.92,3526.04 2303.86,3526.04 2307.82,3530 v1(2405,3530)
  Bottom Layer w6: v1(2151.89,3584.07) 2153.33,3584.07 2169.64,3567.77 U2.38
M0_CL: U2.39 U3.2 | length 441.3
  Top Layer w6: v1(2085,3375) 2150.41,3375 U3.2
  Sign w6: v1(2085,3375) 2085,3570.46 2125,3610.46 v1(2125,3612)
  Bottom Layer w6: v1(2125,3612) 2126,3611 2155.69,3611 U2.39
M0_GH_A: R11.2 U2.6 | length 348.7
  Bottom Layer w6: U2.6 2327.02,3545.54 2327.02,3550.05 2337,3560.04 2337,3709.27 2417.73,3790 R11.2
M0_GH_B: R12.2 U2.15 | length 196.9
  Bottom Layer w6: U2.15 2307.49,3372.96 2315.8,3364.65 2315.8,3353.75 2369.54,3300 2434.3,3300 2454.3,3320 R12.2
M0_GH_C: R13.2 U2.16 | length 225.6
  Bottom Layer w6: U2.16 2293.57,3359.04 2302.3,3350.32 ; 2302.3,3350.27 2430.57,3222 2449.8,3222 R13.2
M0_GL_A: R18.2 U2.8 | length 322.4
  Bottom Layer w6: U2.8 2351.97,3514.82 2351.97,3541.07 2361,3550.09 2361,3699.33 2396.67,3735 R18.2
M0_GL_B: R19.2 U2.13 | length 133.3
  Bottom Layer w6: U2.13 2353.84,3385 2444.3,3385 2454.3,3375 R19.2
M0_GL_C: R20.2 U2.18 | length 275.2
  Bottom Layer w6: U2.18 2265.73,3331.21 2278,3318.94 2278,3300.96 2411.96,3167 2449.8,3167 R20.2
M0_SH_A: H1.3 Q2.7 Q2.8 Q2.9 Q2.10 Q5.2 Q5.3 Q5.4 Q5.5 Q5.6 U2.7 | length 516.4
  Sign w6: v1(2480,3760) 2525,3715 v1(2620,3715)
  Bottom Layer w6: U2.7 2339.02,3529.69 2339.02,3545.08 2349,3555.07 2349,3704.3 2404.7,3760 v1(2480,3760)
M0_SH_B: H1.2 Q3.7 Q3.8 Q3.9 Q3.10 Q6.2 Q6.3 Q6.4 Q6.5 Q6.6 U2.14 | length 380.6
  Sign w6: v1(2464.12,3345) 2615,3345 v1(2650,3380)
  Bottom Layer w6: U2.14 2338.01,3373 2352,3373 2403,3322 2422.46,3322 2445.46,3345 v1(2464.12,3345)
M0_SH_C: H1.1 Q4.7 Q4.8 Q4.9 Q4.10 Q7.2 Q7.3 Q7.4 Q7.5 Q7.6 U2.17 | length 458.3
  Sign w6: v1(2350,3255) 2498,3107 v1(2620.28,3107)
  Bottom Layer w6: U2.17 2282.37,3347.84 2290.21,3340 2295.6,3340 2350,3285.6 v1(2350,3255)
M0_SNA: C10.1 C11.1 C12.1 C13.1 C14.1 C15.1 C16.1 C17.1 C18.1 C20.1 CN1.3 CN1.4 CN2.5 CN2.6 CN3.1 R16.2 R17.1 R25.1 R26.1 R27.1 R28.1 R29.1 U2.10 U2.11 U2.20 U2.40 U2.41 U4.5 U5.2 | length 2954.5
  Top Layer w6: C15.1 C15.1@1936.72,3801.72
  Top Layer w10: CN3.1 1913.42,3288.43 C13.1 ; U5.2 1886.58,3463.1 1910.46,3463.1 1919.67,3453.9 C17.1 C14.1 1945.32,3508.9 1966.23,3529.8 1966.23,3538.1 1985.22,3557.09 1989.88,3557.09 1993.13,3560.34 1993.13,3568.84 1989.88,3572.09 1981.11,3572.09 1947.5,3605.7 1945,3605.7 1940,3610.7 1940,3615.7 1926,3629.7 C16.1 1926,3769 C15.1 ; C13.1@1940,3315 C13.1 ; C10.1@2140,3175 C10.1@2115,3150 ; C20.1@2285,3150 C20.1 C10.1@2115,3150 ; C18.1 2593,3127 2648,3127 C12.1 2650,3131.5 2673.8,3155.3 2719.56,3155.3 2726,3148.86 2726,3092.38 ; R28.1 2702.5,3075 2722.94,3095.44 2733.38,3085 v1(2735,3085) ; C13.1 1935,3270 C11.1 C10.1 C10.1@2115,3150
  Bottom Layer w10: R16.2 2030.85,3214.15 2146.02,3214.15 ; 2125,3670 2125,3669.52 U2.40 2218.4,3576.12 U2.41 ; U2.11 2343.68,3450.84 ; U2.11@2369.43,3425.2 2416.56,3425.2 R26.1@2435,3443.64 ; R27.1 2442.01,3103.31 2427.32,3117.99 2420.41,3117.99 2250,3288.4 2250,3293.98 U2.20 2228.15,3315.83 2228.15,3315.94 2223.14,3320.95 2223.14,3327.9 2218.4,3332.64 U2.41 ; R26.1 2435,3466.5 R26.1@2435,3443.64 ; R25.1 2443.5,3678.22 2428.82,3692.91 2395,3692.91 2387,3684.91 2387,3539.33 2380,3532.33 2380,3487.17 U2.10 2343.68,3450.84 ; v1(2444.82,3425.18) 2438.28,3431.72 2435,3431.72 v1(2435,3440) 2436,3441 2435,3442 R26.1@2435,3443.64 ; U2.41 2343.68,3450.84
  other v1: 1925,3095 1945,3095 1965,3095 1985,3095 2005,3095 2025,3095 2045,3095 2065,3095 2085,3095 2105,3095 2125,3095 2145,3095 2165,3095 2185,3095 2205,3095 2225,3095 2245,3095 2265,3095 1905,3115 1925,3115 1945,3115 1965,3115 1985,3115 2005,3115 2025,3115 2045,3115 2065,3115 2085,3115 2105,3115 2125,3115 2145,3115 2165,3115 2185,3115 2205,3115 2225,3115 2245,3115 2265,3115 2285,3115 2125,3175 2145,3175 2165,3175 2185,3175 2205,3175 2225,3175 2245,3175 2265,3175 1745,3180 1765,3180 1785,3180 1805,3180 1825,3180 1845,3180 1865,3180 1945,3185 1965,3185 1985,3185 2005,3185 2025,3185 2045,3185 2065,3185 2085,3185 2105,3185 2125,3195 2145,3195 2165,3195 2185,3195 2205,3195 2225,3195 2245,3195 1745,3200 1765,3200 1785,3200 1805,3200 1825,3200 1845,3200 1865,3200 1885,3200 1745,3220 1765,3220 1785,3220 1805,3220 1825,3220 1845,3220 1865,3220 1885,3220 1905,3220 1745,3240 1765,3240 1785,3240 1805,3240 1825,3240 1845,3240 1865,3240 1885,3240 1905,3240 1845,3260 1865,3260 1745,3335 1765,3335 1785,3335 1805,3335 2455,3440 2435,3460 2454.82,3459.82 2443,3589.77 1860,3765 1860,3785 1860,3805 1880,3805 1860,3825 1880,3825 1860,3845 1880,3845 1900,3845 1920,3845 1940,3845
M0_SOA: U2.23 U3.5 | length 125.6
  Top Layer w6: v1(2151.79,3314.29) 2152.5,3315 2173.92,3315 U3.5
  Bottom Layer w6: v1(2151.79,3314.29) 2151.79,3314.46 2171.08,3333.75 U2.23
M0_SOB: U2.22 U3.6 | length 127.1
  Top Layer w6: v1(2170,3295) 2171.91,3296.91 2183.68,3296.91 U3.6
  Bottom Layer w6: v1(2170,3295) 2170.75,3295.75 2170.75,3305.75 U2.22
M0_SOC: U2.21 U3.7 | length 127.4
  Top Layer w6: v1(2190,3275) 2190,3275.41 U3.7
  Bottom Layer w6: v1(2190,3275) 2190,3277.71 2192.65,3280.36 2192.65,3297.1 2198.92,3303.37 U2.21
M0_SPA: Q5.7 Q5.8 Q5.9 Q5.10 R25.2 U2.9 | length 416.5
  Bottom Layer w6: U2.9 2365.36,3500.36 2365.36,3537.48 2373,3545.12 2373,3694.36 2388.64,3710 2475,3710 2489.81,3695.19 2489.81,3651.68 R25.2
M0_SPB: Q6.7 Q6.8 Q6.9 Q6.10 R26.2 U2.12 | length 221
  Bottom Layer w6: U2.12 2366.69,3400 2475,3400 2489.81,3414.81 2489.81,3458.32 R26.2
M0_SPC: Q7.7 Q7.8 Q7.9 Q7.10 R27.2 U2.19 | length 392
  Bottom Layer w6: U2.19 2251.81,3317.28 2266,3303.09 2266,3295.99 2420.99,3141 2467.31,3141 2505,3103.31 R27.2
NetC3_2: C3.2 R7.2 S1.2 U3.4 | length 916.5
  Top Layer w6: v1(2145,3285) 2130,3300 2130,3325 2140,3335 2166.08,3335 U3.4 ; v1(2565,3255) 2577.02,3242.98 2588,3242.98 2595,3235.98 R7.2
  Top Layer w10: R7.2 C3.2 2657.5,3235 2672.55,3250.05 S1.2@2672.55,3434.02
  Sign w6: v1(2145,3285) 2175,3255 2200,3255 2223,3278 2274.27,3278 2285.27,3267 2336.54,3267 2342.54,3273 2546.54,3273 2564.54,3255 v1(2565,3255)
NetC4_1: C4.1 U2.3 | length 128.9
  Bottom Layer w6: U2.3 2265.73,3570.48 2274.03,3578.78 2274.03,3655.03 2290.5,3671.5 2293,3671.5 2300,3678.5 C4.1
NetC4_2: C4.2 U2.4 | length 90.9
  Bottom Layer w6: U2.4 2279.65,3556.57 2287.96,3564.88 2287.96,3620.46 C4.2@2302.7,3635.2
NetC6_1: C6.1 U2.1 | length 108.7
  Bottom Layer w6: C6.1 2211.5,3685 2218.5,3678 2245,3651.5 2245,3605.44 2237.89,3598.33 U2.1
NetC6_2: C6.2 U2.2 | length 100
  Bottom Layer w6: C6.2 2260.11,3679.89 2260.11,3592.71 2258.07,3590.67 U2.2@2258.07,3587.95
NetC7_2: C7.2 L1.2 U3.15 | length 129.7
  Top Layer w10: U3.15 2394.6,3410.19 2429.79,3375 C7.2 2431.77,3376.77 2464.36,3376.77 2495,3346.13 L1.2
NetC9_1: C9.1 U4.4 | length 100.2
  Top Layer w10: U4.4 2475.91,3181.5 2513.37,3181.5 2530,3198.13 2530,3229 C9.1
NetC9_2: C9.2 L2.1 U4.6 | length 27.7
  Top Layer w10: L2.1 2475.48,3261.38 L2.1@2494.1,3280
NetC18_2: C18.2 U4.2 | length 71.8
  Top Layer w10: U4.2 2475.91,3128.5 2541.5,3128.5 C18.2
NetL3_1: L3.1 U5.3 | length 113.7
  Top Layer w10: L3.1 1814.68,3590 1877.83,3526.86 ; U5.3@1877.83,3509.26 U5.3
NetLED1_1: LED1.1 Q1.2 | length 106.6
  Top Layer w14: Q1.2 2614.65,3670.35 LED1.1
NetLED2_1: LED2.1 R9.2 | length 86.8
  Top Layer w14: R9.2 2590,3782.5 2593,3785.5 2595.5,3785.5 2615,3805 LED2.1
NetQ1_3: Q1.3 R10.1 | length 226.1
  Top Layer w14: Q1.3 2489.48,3679.38 2465.62,3679.38 2450,3695 2450,3770 2466,3786 2523.8,3786 2524.3,3785.5 2532,3785.5 2535,3782.5 R10.1
NetQ2_1: Q2.1 R11.1 | length 373.4
  Sign w6: v1(2510,3811) 2511,3810 2801.49,3810 v1(2842.83,3768.66)
  Bottom Layer w6: R11.1 2510,3795 v1(2510,3811)
NetQ3_1: Q3.1 R12.1 | length 407.5
  Sign w6: v1(2519,3308.69) 2520,3309.69 2609.69,3309.69 2765.53,3465.53 v1(2842.83,3465.53)
  Bottom Layer w6: R12.1 2507.5,3320 2518.81,3308.69 v1(2519,3308.69)
NetQ4_1: Q4.1 R13.1 | length 367.9
  Sign w6: v1(2505.08,3201.5) 2505.59,3202 2803.19,3202 v1(2842.79,3162.4)
  Bottom Layer w6: R13.1 2505.08,3214.92 v1(2505.08,3201.5)
NetQ5_1: Q5.1 R18.1 | length 141.6
  Sign w6: v1(2510,3760) 2609.53,3760 2618.19,3768.66 v1(2620.89,3768.66)
  Bottom Layer w6: R18.1 2505,3752.29 2510,3757.29 v1(2510,3760)
NetQ6_1: Q6.1 R19.1 | length 160.6
  Sign w6: v1(2510,3390) 2545,3390 v1(2620,3465)
  Bottom Layer w6: R19.1@2507.5,3375 R19.1 2510,3380 v1(2510,3390)
NetQ7_1: Q7.1 R20.1 | length 121.2
  Sign w6: v1(2535,3150) 2611.75,3150 2616.75,3155 v1(2620,3155)
  Bottom Layer w10: R20.1 2510,3155 2527.84,3155 2532.84,3150 v1(2535,3150)
NetR2_2: R2.2 U3.31 | length 63.5
  Top Layer w10: R2.2 2147.5,3525 2152.5,3520 2152.5,3512.9 U3.31
NetR6_1: R6.1 U2.30 | length 57.5
  Bottom Layer w10: R6.1 2052.29,3410 U2.30
NetR21_2: R21.2 U4.3 | length 78.3
  Top Layer w10: U4.3 2475.09,3155.09 2509.59,3155.09 2524.5,3170 2540,3170 R21.2
NetR22_1: R22.1 R24.2 R28.2 | length 138.9
  Top Layer w10: R24.2 R28.2 2654.3,3075 2700,3120.7 2700,3126.8 R22.1
NetR23_1: R23.1 R29.2 U5.5 | length 294.1
  Top Layer w10: R23.1 R29.2
  Top Layer w14: v1(1775,3405) 1778.82,3408.82 U5.5
  Bottom Layer w14: v1(1775,3405) 1775,3475 v1(1875,3575)
NetR24_1: R24.1 U4.1 | length 83.4
  Top Layer w10: U4.1 2516.18,3103.82 2537.5,3082.5 2537.5,3080 2542.5,3075 R24.1
nFAULT: R5.2 U2.25 U3.11 | length 407.2
  Top Layer w6: U3.11 2339.6,3354.51 2364.11,3330 v1(2365,3330)
  Sign w6: v1(2108.74,3327.37) 2111.45,3327.37 2129.08,3345 2241.13,3345 2258.13,3328 2313.44,3328 2317.6,3323.84 2336.6,3323.84 2342.75,3330 v1(2365,3330)
  Bottom Layer w10: R5.2 2066.77,3323.23 2102.44,3323.23 2106.58,3327.37 v1(2108.74,3327.37) ; v1@2108.09,3326.61 2108.09,3326.66 U2.25 U2.25
SPI_MISO: H2.5 U3.27 | length 896
  Top Layer w6: U3.27 2241.28,3539.03 2231,3549.31 2231,3606 2282,3657 2435.17,3657 2577.17,3515 2885,3515 2917.05,3482.95 H2.5
SPI_MOSI: H2.6 U3.28 | length 915.1
  Top Layer w6: U3.28 2227.36,3525.11 2217.25,3535.23 2217.25,3609.22 2277.03,3669 2441,3669 2577.84,3532.16 H2.6
SPI_NSS: H2.3 U3.25 | length 873.8
  Top Layer w6: U3.25 2269.12,3566.87 2255,3580.99 2255,3595.03 2292.97,3633 2425.23,3633 2573.23,3485 2860,3485 2916.51,3428.49 2916.51,3405.36 2925.07,3396.81 2937.36,3384.52 H2.3
SPI_SCK: H2.4 U3.26 | length 877.8
  Top Layer w6: U3.26 2255.2,3552.95 2243,3565.15 2243,3600 2288,3645 2430.2,3645 2575.2,3500 2870,3500 2927.45,3442.55 2950.2,3442.55 H2.4
State_LED: Q1.1 U3.10 | length 556.4
  Top Layer w6: U3.10 2324.8,3339.45 2339.2,3325.05 2339.2,3299.2 v1(2325,3285)
  Sign w6: v1(2325,3285) 2385.46,3285 2436.95,3336.49 2436.95,3346.95 2575,3485 v1(2575,3635)
SWCLK: CN2.3 R15.1 U3.24 | length 658.5
  Top Layer w10: v1(2307,3580) 2316.92,3570.08 2316.92,3569.36 U3.24
  Sign w6: v1(2014.89,3437.5) 2014.89,3481.53 2040,3506.64 2040,3547.43 2020,3567.43 2020,3585 2090,3655 2230,3655 2305,3580 v1(2307,3580)
  Bottom Layer w6: R15.1 1975,3422.5 1982,3429.5 1984.5,3429.5 1992.5,3437.5 v1(2014.89,3437.5)
  Bottom Layer w10: CN2.3 1902.83,3419.37 1974.37,3419.37 R15.1
SWDIO: CN2.4 R14.2 U3.23 | length 848.1
  Top Layer w6: v1(2307,3607.5) 2334.91,3579.59 2334.91,3563.07 2324.79,3552.95 U3.23
  Sign w6: v1(2000,3330) 2018,3348 2018,3408.93 1996.89,3430.04 1996.89,3480.5 2028,3511.61 2028,3542.46 2008,3562.46 2008,3593 2085,3670 2240,3670 2289.9,3620.1 2294.14,3620.1 2306.74,3607.5 v1(2307,3607.5)
  Bottom Layer w10: CN2.4 1961.17,3369.53 1975,3355.7 R14.2 1975,3350.7 1994.55,3331.15 1998.85,3331.15 v1(2000,3330)
VCC: C10.2 C11.2 C12.2 C20.2 CN3.2 H2.7 H2.8 Q2.2 Q2.3 Q2.4 Q2.5 Q2.6 Q3.2 Q3.3 Q3.4 Q3.5 Q3.6 Q4.2 Q4.3 Q4.4 Q4.5 Q4.6 R3.2 R6.2 R21.1 U2.5 U4.7 | length 1543.1
  Top Layer w10: R21.1 2597.2,3179 2646,3179 C12.2 2650,3177.5 2681.76,3209.26 2865.17,3209.26
  Sign w6: v1(2454.3,3832.87) 2455.74,3831.44 2993.56,3831.44 v2(2995,3830)
  Bottom Layer w6: v1(1850,3090) 1850,3139.05 2018.23,3307.28 2018.23,3355.03 R6.2 ; U2.5 2293.97,3539.93 2325,3570.96 2325,3714.25 2442.24,3831.48 2452.91,3831.48 v1(2454.3,3832.87)
  other v2: 2985,2995 3010,2995 3035,2995 3060,2995 3085,2995 3110,2995 2985,3020 3010,3020 3035,3020 3060,3020 3085,3020 3110,3020 2985,3045 3010,3045 3035,3045 3060,3045 3085,3045 3110,3045 2985,3070 3010,3070 3035,3070 3060,3070 3085,3070 3110,3070 2985,3095 3010,3095 3035,3095 3060,3095 3085,3095 3110,3095 2985,3120 3010,3120 3035,3120 3060,3120 3085,3120 3110,3120 2985,3145 3010,3145 3035,3145 3060,3145 3085,3145 3110,3145 2985,3170 3010,3170 3035,3170 3060,3170 3085,3170 3110,3170 2815,3340 2875,3340 2815,3360 2875,3360 2815,3380 2840,3380 2865,3380 2890,3380 2815,3400 2875,3400 2815,3420 2875,3420 2995,3730 3020,3730 3045,3730 3070,3730 3095,3730 3120,3730 2995,3755 3020,3755 3045,3755 3070,3755 3095,3755 3120,3755 2995,3780 3020,3780 3045,3780 3070,3780 3095,3780 3120,3780 2995,3805 3020,3805 3045,3805 3070,3805 3095,3805 3120,3805 3020,3830 3045,3830 3070,3830 3095,3830 3120,3830
VCC_ADC: R3.1 R4.2 U3.8 | length 753.7
  Top Layer w6: v1(2245,3260) 2245,3302.56 U3.8
  Top Layer w14: R3.1 R4.2
  Sign w6: v1(2245,3260) 2245,3235 2407.54,3072.46 2637.46,3072.46 2685,3120 v1(2750,3120)
pads on no net: U1.5 U3.3 U3.29 U3.30 U4.8

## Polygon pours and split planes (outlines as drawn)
DGND on Top Layer "DGND_L01_P025" (solid, pour order 25): 1965,3860 2845,3860 2845,3560 3010,3560 3010,3250 2920,3250 2915,3255 2915,3430 2870,3475 2780,3475 2780,3100 2745,3065 2570,3065 2570,3290 2540,3320 2360,3320 2350,3310 2350,3270 2335,3255 2175,3255 2055,3375 2020,3375 2010,3385 2010,3525 2020,3535 2020,3590 2015,3595 1990,3595 1970,3615 1970,3680 1965,3685
NetC9_2 on Top Layer "NETC9_2_L01_P023" (solid, pour order 23): 2354,3146 2430,3146 2440,3156 2440,3191 2445,3196 2490,3196 2514,3220 2514,3258 2518,3262 2549,3262 2549,3307 2546,3310 2432,3310 2432,3217 2432,3210 2424,3202 2424,3168 2419,3163 2354,3163
5V on Top Layer "5V_L01_P003" (solid, pour order 3): 1730,3520 1730,3455 1805,3455 1895,3365 1950,3365 1970,3345 1970,3212 2105,3212 2258,3212 2425,3212 2425,3310 2370,3310 2360,3300 2360,3245 2270,3245 2175,3245 2060,3360 2020,3360 1945,3435 1915,3435 1905,3445 1860,3445 1840,3465 1840,3520
M0_SNA on Top Layer "M0_SNA_L01_P024" (solid, pour order 24): 1845,3860 1950,3860 1950,3680 1960,3670 1960,3610 1985,3585 2010,3585 2010,3545 1985,3545 1960,3520 1960,3445 1915,3445 1905,3455 1860,3455 1850,3465 1850,3480 1915,3480 1915,3520 1960,3565 1960,3580 1950,3590 1910,3590 1910,3690 1845,3755
M0_SNA on Top Layer "M0_SNA_L01_P002" (solid, pour order 2): 1730,3155 1840,3155 1910,3085 2280,3085 2345,3150 2345,3165 2350,3170 2415,3170 2415,3205 2160,3205 2120,3205 2110,3195 1965,3195 1955,3205 1955,3340 1945,3350 1730,3350
VCC on Top Layer "Top Layer-VCC" (solid, pour order 21): 3135,2960 3140,2965 3140,3850 2860,3850 2860,3570 3020,3570 3020,3240 2915,3240 2905,3250 2905,3425 2870,3460 2790,3460 2790,3125 2715,3050 2390,3050 2350,3090 2350,3115 2355,3120 2415,3120 2415,3138 2348,3138 2285,3075 1895,3075 1835,3135 1730,3135 1730,2960
+3.3V on Top Layer "+3.3V_L01_P005" (solid, pour order 5): 1860,3590 1900,3590 1900,3685 1830,3755 1830,3860 1730,3860 1730,3635 1860,3635
NetL3_1 on Top Layer "NETL3_1_L01_P004" (solid, pour order 4): 1730,3530 1730,3620 1850,3620 1850,3565 1905,3510 1905,3490 1850,3490 1850,3530
M0_SNA on Bottom Layer "M0_SNA_L06_P028" (solid, pour order 28): 2465,3700 2475,3690 2475,3420 2465,3410 2390,3410 2390,3690 2400,3700
M0_SH_C on Bottom Layer "M0_SH_C_L06_P013" (solid, pour order 13): 2590,3015 2590,3135 2655,3135 2655,3195 2740,3195 2740,3255 2960,3255 2970,3265 2970,3365 3015,3410 3140,3410 3140,3215 3130,3205 2790,3205 2790,3000 2950,3000 2950,2960 2740,2960 2740,3015
M0_SNA on Bottom Layer "M0_SNA_L06_P029" (solid, pour order 29): 1730,3860 2435,3860 2435,3840 2320,3725 2295,3725 2275,3705 2190,3705 2005,3520 2005,3265 2045,3225 2140,3225 2175,3260 2260,3260 2460,3060 2460,2960 1730,2960
M0_SPC on Bottom Layer "M0_SPC_L06_P008" (solid, pour order 8): 2730,2960 2480,2960 2480,3125 2485,3130 2535,3130 2535,3255 2730,3255 2730,3205 2580,3205 2580,3005 2730,3005
VCC on Bottom Layer "VCC_L06_P016" (solid, pour order 16): 2800,3620 2945,3620 3020,3695 3140,3695 3140,3850 2960,3850 2960,3795 2880,3795 2880,3745 2800,3745
M0_SH_A on Bottom Layer "Bottom Layer-M0_SH_A" (solid, pour order 11): 2590,3620 2740,3620 2740,3565 2950,3565 2955,3560 3140,3560 3140,3680 3020,3680 2950,3610 2790,3610 2790,3805 2950,3805 2950,3850 2740,3850 2740,3790 2655,3790 2655,3745 2590,3745
VCC on Bottom Layer "VCC_L06_P015" (solid, pour order 15): 2800,3135 2875,3135 2875,3195 3130,3195 3140,3185 3140,2965 3135,2960 2960,2960 2960,3010 2800,3010
VCC on Bottom Layer "VCC_L06_P014" (solid, pour order 14): 2800,3440 2875,3440 2875,3495 2930,3495 2995,3430 2995,3405 2950,3360 2950,3320 2800,3320
M0_SH_B on Bottom Layer "M0_SH_B_L06_P012" (solid, pour order 12): 2590,3320 2590,3440 2655,3440 2655,3490 2740,3490 2740,3545 3140,3545 3140,3425 3015,3425 2935,3505 2790,3505 2790,3310 2950,3310 2950,3265 2740,3265 2740,3320
M0_SPB on Bottom Layer "M0_SPB_L06_P007" (solid, pour order 7): 2480,3545 2730,3545 2730,3500 2580,3500 2580,3310 2730,3310 2730,3265 2535,3265 2535,3395 2525,3405 2485,3405 2480,3410
M0_SPA on Bottom Layer "M0_SPA_L06_P006" (solid, pour order 6): 2480,3565 2730,3565 2730,3610 2580,3610 2580,3800 2730,3800 2730,3850 2545,3850 2530,3835 2530,3705 2480,3705
M0_SNA on Sign "NONET_L-01_P-001" (solid, pour order 33): 3135,3855 1735,3855 1735,2965 3135,2965
AGND on Sign "AGND_L04_P027" (solid, pour order 27): 1980,3210 1980,3450 2020,3490 2020,3590 1935,3590 1935,3210
M0_SNA on GND1 "NONET_L-01_P-001" (solid, pour order 31): 2950,3855 1735,3855 1735,2965 2950,2965
VCC on GND1 "NONET_L-01_P-001" (solid, pour order 30): 3135,3855 3135,2965 2960,2965 2960,3855
M0_SNA on GND "M0_SNA_L03_P026" (solid, pour order 26): 1735,3860 1735,2965 3135,2965 3135,3855
M0_SNA on GND2 "NONET_L-01_P-001" (solid, pour order 32): 3135,3855 1735,3855 1735,2965 3135,2965

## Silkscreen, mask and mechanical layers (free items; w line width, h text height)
Mechanical 1:
  the board outline again, w10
